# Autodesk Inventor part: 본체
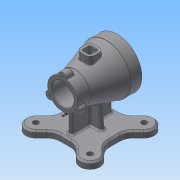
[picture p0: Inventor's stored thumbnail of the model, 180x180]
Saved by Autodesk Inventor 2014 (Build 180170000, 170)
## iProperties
Created: 2018-03
Part Number: 본체
Material: 일반
Document SubType Name: Modeling
Designer: 601-11
Density: 1 g/cm^3
Appearance: 기본값
Mass: 373.775 g
Surface Area: 852.813 cm^2
Volume: 373.775 cm^3
Author: 601-11
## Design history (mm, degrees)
sketch "스케치1"
  geometry: L1 (0, 0)-(50, 0); L2 (50, 0)-(-50, 0); L3 (-50, 35)-(-50, 45); L4 (-50, 45)-(-30, 45); L5 (50, 27.5)-(27, 27.5); L6 (27, 27.5)-(-30, 45); L7 (50, 20)-(20, 20); L8 (50, 20)-(50, 27.5); L9 (20, 20)-(20, 26); L10 (20, 26)-(-27, 26); L11 (-27, 26)-(-27, 35); L12 (-27, 35)-(-50, 35)
  constraints: 24 end point, 5 perpendicular, 3 parallel, 1 horizontal
  dimensions: "d1" = 100 distance of L1.end L2.end; "d3" = 90 diameter of L3.end L2; "d4" = 20 distance of L3.end L4.end; "d5" = 55 diameter of L5.start L2; "d6" = 77 distance from line of L3 L5.end; "d8" = 30 distance of L7.start L7.end; "d9" = 40 diameter of L7.start L2; "d10" = 47 distance of L9.end L10.end; "d11" = 70 diameter of L12 L2; "d12" = 52 diameter of L10 L2
revolve "회전1" sketch "스케치1" stored, may be unused: angle "d13" = 90 deg
node "작업 평면1"
sketch "스케치2"
  geometry: L1 (0, 0)-(45, 0); L2 (0, 0)-(-45, 0); L3 (0, 0)-(0, 45); L4 (0, 0)-(0, -45); L5 (-45.962, -45.962)-(-49.497, -49.497); L6 (-26.869, 52.322)-(-36.772, 62.225); L7 (-45, 0)-(-45, 9.174); L8 (-45, 9.174)-(-45, -9.189); L9 (-52.322, -26.866)-(-62.225, -36.77); L10 (-26.866, -52.322)-(-36.77, -62.225); L11 (26.931, -52.322)-(35.897, -61.288); L12 (52.322, -26.866)-(62.225, -36.77); L13 (52.322, 26.866)-(62.225, 36.77); L14 (26.866, 52.322)-(36.77, 62.225); L15 (0, 45)-(19.544, 45); L16 (9.189, 45)-(-9.191, 45); L17 (45, 9.189)-(45, -9.189); L18 (0, -45)-(19.544, -45); L19 (9.253, -45)-(-9.189, -45); L20 (-43.272, -45)-(43.272, 45); L21 (62.225, -62.225)-(-44.144, 44.144); L22 (-52.331, 26.873)-(-62.227, 36.77); L23 (-49.5, 49.497)-(49.497, 49.497); L24 (-53.033, -53.033)-(75.027, 75.027); C1 r 5 at (-49.5, 49.497); C2 r 5 at (49.497, 49.497); C3 r 5 at (49.497, -49.497); A1 r 5 centre (-49.497, -49.497) between (-45.962, -45.962) and (-53.033, -53.033); A2 r 18 centre (49.497, 49.497) between (62.225, 36.77) and (36.77, 62.225); A3 r 18 centre (49.497, -49.497) between (35.897, -61.288) and (62.225, -36.77); A4 r 18 centre (-49.497, -49.497) between (-62.225, -36.77) and (-36.77, -62.225); A5 r 25.031 centre (-70.031, 9.174) between (-45, 9.174) and (-52.331, 26.873); A6 r 25 centre (-70, -9.189) between (-52.322, -26.866) and (-45, -9.189); A7 r 25 centre (-9.189, -70) between (-9.189, -45) and (-26.866, -52.322); A8 r 25 centre (9.253, -70) between (26.931, -52.322) and (9.253, -45); A9 r 25 centre (70, -9.189) between (45, -9.189) and (52.322, -26.866); A10 r 25 centre (70, 9.189) between (52.322, 26.866) and (45, 9.189); A11 r 25 centre (-9.191, 70) between (-26.869, 52.322) and (-9.191, 45); A12 r 25 centre (9.189, 70) between (9.189, 45) and (26.866, 52.322); A13 r 18 centre (-49.5, 49.497) between (-36.772, 62.225) and (-62.227, 36.77); A14 r 70 centre (0, 0) between (-49.497, -49.497) and (49.497, -49.497)
  constraints: 48 end point, 29 point on circle, 17 centre point, 16 tangent, 7 coincident, 5 collinear, 5 parallel, 5 point on line, 3 perpendicular, 2 midpoint, 1 horizontal
  dimensions: "d18" = 45 distance of L2.start L3.end; "d19" = 45 distance of L2.start L4.end; "d23" = 10 diameter of C1; "d24" = 10 diameter of C2; "d25" = 10 diameter of C3; "d26" = 10 diameter of A1; "d29" = 36 diameter of A3; "d30" = 36 diameter of A4; "d40" = 18 distance between parallel lines of L5 L10; "d41" = 50 diameter of A7; "d42" = 50 diameter of A8; "d50" = 18 radius of A2; "d56" = 21.29566 dimension on L15.end L2.start C2.centre; "d129" = 45 distance from line of L1.start L8; "d130" = 45 distance from line of L1.start L17; "d132" = 36 diameter of A13; "d133" = 140 diameter of A14; "d134" = 45 deg angle of L1 L24; "d136" = 45 deg angle of L1 L21
extrude "돌출1" join sketch "스케치2" distance "d57" = 12; taper "d58" = 0 deg
chamfer "모따기1" distance "d59" = 3; stored, may be unused: second distance "d60" = 2, angle "d61" = 45 deg
sketch "스케치3"
  geometry: L1 (-42, -9.189)-(-42, 9.189) reference; L2 (42, 9.189)-(42, -9.174) reference; L3 (0, 0)-(-37, 0); L4 (-37, 0)-(-37, -4); L5 (-37, -4)-(37, -4); L6 (37, -4)-(37, 4); L7 (37, 4)-(-37, 4); L8 (-37, 4)-(-37, -4)
  constraints: 12 end point, 3 perpendicular, 2 parallel
  dimensions: "d62" = 37 distance of L3.start L3.end; "d63" = 4 distance of L3.end L4.end; "d64" = 74 distance of L4.end L5.end; "d65" = 8 distance of L5.end L6.end; "d66" = 74 distance of L6.end L7.end
extrude "돌출2" join sketch "스케치3" stored distance "d67" = 0; taper "d68" = 0 deg
sketch "스케치5"
  geometry: L1 (-70, 0)-(-70, -24); L2 (-70, -28.988)-(-70, -9.189) reference; L3 (-70, -24)-(-22.037, -19.804); L4 (-70, 0)-(-70, 24); L5 (-70, 9.189)-(-70, 28.988) reference; L6 (-70, 24)-(-22.037, 19.804); L7 (-70, 24)-(-70, -24); A1 r 28.892 centre (-1, 0) between (-22.037, 19.804) and (-22.037, -19.804); 1 further point
  constraints: 10 end point, 2 point on circle, 2 point on line, 1 centre point, 1 collinear
  dimensions: "d69" = 24 distance of L1.start L1.end; "d73" = 24 distance of L1.start L4.end; "d74" = 95 deg angle of L4 L6
extrude "돌출3" join sketch "스케치5" stored distance "d75" = 8; taper "d76" = 0 deg
chamfer "모따기2" distance "d78" = 1; stored, may be unused: second distance "d79" = 2, angle "d80" = 45 deg
sketch "스케치7"
  geometry: L1 (0, 0)-(0, 34); C1 r 27.5 at (0, 0) reference; C2 r 21 at (0, 0) reference; A1 r 7 centre (0, 27.5) between (6.943, 26.609) and (-6.943, 26.609); A2 r 7 centre (-23.816, -13.75) between (-26.516, -7.292) and (-19.573, -19.317); A3 r 7 centre (23.816, -13.75) between (19.573, -19.317) and (26.516, -7.292); A4 r 27.5 centre (0, 0) between (6.943, 26.609) and (-6.943, 26.609); A5 r 27.5 centre (0, 0) between (-26.516, -7.292) and (-19.573, -19.317); A6 r 27.5 centre (0, 0) between (19.573, -19.317) and (26.516, -7.292)
  constraints: 13 point on circle, 6 centre point, 2 end point, 1 coincident, 1 point on line, 1 vertical, 13 other
  dimensions: "d82" = 14 diameter of A1; "d85" = 360 deg dimension on C1.centre A1.centre (derived)
extrude "돌출4" join sketch "스케치7" distance "d87" = 15; taper "d88" = 0 deg
sketch "스케치8"
  geometry: A1 r 7 centre (-23.816, -41.25) between (-26.516, -34.792) and (-19.573, -46.817) reference; A2 r 7 centre (23.816, -41.25) between (19.573, -46.817) and (26.516, -34.792) reference; A3 r 7 centre (0, 0) between (6.943, -0.891) and (-6.943, -0.891) reference; 3 further points
  constraints: 3 coincident
hole "구멍1" sketch "스케치8" at (0, 0), (-23.816, -41.25), (23.816, -41.25) diameter "d89" = 3.242; stored, may be unused: countersink angle "d93" = 90 deg, drill point angle "d95" = 118 deg; dims "d90" = 9, "d91" = 4, "d92" = 2, "d94" = 11
fillet "모깎기1" dims "d96" = 3
fillet "모깎기2" dims "d97" = 1, "d98" = 3
fillet "모깎기3" dims "d99" = 3
sketch "스케치9" dims "d100" = 80
  geometry: C1 r 36 at (0, 0) reference; 7 further points
  constraints: 1 coincident, 1 vertical alignment, 9 other
  dimensions: "d103" = 360 deg dimension on point (0, 0) point (0, 40) (derived)
hole "구멍2" sketch "스케치9" at (0, 40), (-34.641, 20), (-34.641, -20), (0, -40), (34.641, -20), (34.641, 20) diameter "d105" = 3.242; stored, may be unused: countersink angle "d109" = 90 deg, drill point angle "d111" = 118 deg; dims "d106" = 9, "d107" = 4, "d108" = 2, "d110" = 11
sketch "스케치10"
  geometry: L1 (45, -9.174)-(45, 9.189) reference; 2 further points
  constraints: 1 other
  dimensions: "d112" = 45 distance from line of L1 point (0, -35); "d113" = 35 distance of point (0, 0) point (0, -35)
feature "엠보싱1" sketch "스케치10" dims "d1" = 100, "d3" = 90, "d4" = 20, "d5" = 55, "d6" = 77, "d8" = 30, "d9" = 40, "d10" = 47, "d11" = 70, "d12" = 52, "d18" = 45, "d19" = 45, "d23" = 10, "d24" = 10, "d25" = 10, "d26" = 10, "d29" = 36, "d30" = 36, "d40" = 18, "d41" = 50, "d42" = 50, "d50" = 18, "d56" = 21.29566, "d114" = 0.5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
node "작업 평면3"
sketch "스케치11"
  geometry: L1 (-12.5, -12.5)-(12.5, -12.5); L2 (12.5, -12.5)-(12.5, 12.5); L3 (12.5, 12.5)-(-12.5, 12.5); L4 (-12.5, 12.5)-(-12.5, -12.5); L5 (-12.5, -12.5)-(12.5, 12.5); L6 (12.5, -12.5)-(-12.5, 12.5); L7 (-7.5, -7.5)-(7.5, -7.5); L8 (7.5, -7.5)-(7.5, 7.5); L9 (7.5, 7.5)-(-7.5, 7.5); L10 (-7.5, 7.5)-(-7.5, -7.5); L11 (-7.5, -7.5)-(7.5, 7.5); L12 (7.5, -7.5)-(-7.5, 7.5); 1 further point
  constraints: 24 end point, 4 midpoint, 4 parallel, 2 horizontal, 2 perpendicular
  dimensions: "d117" = 25 distance of L3.end L2.end; "d118" = 25 distance of L1.end L2.end; "d119" = 15 distance of L9.end L8.end; "d120" = 15 distance of L7.end L8.end
extrude "돌출5" join sketch "스케치11" stored distance "d121" = 0; taper "d122" = 0 deg
extrude "돌출6" cut sketch "스케치11" stored distance "d123" = 15; taper "d124" = 0 deg
fillet "모깎기4" dims "d125" = 3, "d126" = 8
fillet "모깎기5" dims "d127" = 1
node "솔리드1"
other parameters: "d14" = -82, "d21" = 45 deg, "d31" = 18, "d33" = 18, "d36" = 18, "d37" = 18, "d81" = 55, "d116" = 45
